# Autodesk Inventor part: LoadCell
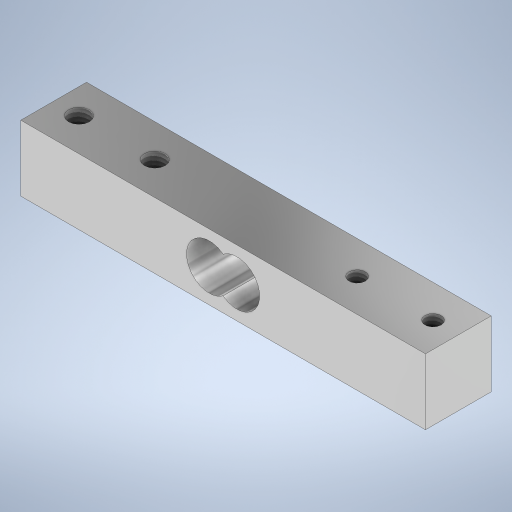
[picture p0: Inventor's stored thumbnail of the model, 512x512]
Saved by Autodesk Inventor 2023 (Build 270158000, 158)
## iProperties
Created: 2023-08
Part Number: LoadCell
Material: Generic
Document SubType Name: Modeling
Designer: Admin
Density: 1 g/cm^3
Appearance: Aluminum - Polished
Author: Admin
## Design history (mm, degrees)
sketch "Sketch1"
  geometry: L1 (0, 0)-(80, 0); L2 (80, 0)-(80, -13); L3 (80, -13)-(0, -13); L4 (0, -13)-(0, 0); L5 (80, -6.5)-(0, -6.5); C1 r 2 at (75, -6.5); C2 r 2 at (60, -6.5); C3 r 1.5 at (20, -6.5); C4 r 1.5 at (5, -6.5)
  constraints: 10 end point, 4 centre point, 3 horizontal alignment, 2 equal radius, 2 midpoint, 2 parallel, 1 horizontal, 1 perpendicular, 1 point on line
  dimensions: "d0" = 13 distance between parallel lines of L1 L3; "d1" = 15 distance of C1.centre C2.centre; "d2" = 80 distance between parallel lines of L4 L2; "d3" = 15 distance of C4.centre C3.centre; "d4" = 5 distance from line of L4 C4.centre; "d5" = 5 distance from line of L2 C1.centre; "d6" = 4 diameter of C1; "d7" = 3 diameter of C3
extrude "Extrusion1" new body sketch "Sketch1" distance "d8" = 13; taper "d9" = 0 deg
sketch "Sketch2"
  geometry: L1 (80, 0)-(80, 13) reference; L2 (80, 6.5)-(0, 6.5); L3 (0, 0)-(0, 13) reference; L4 (0, 13)-(80, 13) reference; L5 (40, 13)-(42.733, 6.5); L6 (37.267, 6.5)-(40, 13); C1 r 4.5 at (42.733, 6.5); C2 r 4.5 at (37.267, 6.5); 2 further points
  constraints: 6 end point, 3 midpoint, 2 centre point, 2 point on line, 1 equal length, 1 equal radius
  dimensions: "d10" = 9 diameter of C1
extrude "Extrusion2" cut sketch "Sketch2" stored distance "d11" = 13; taper "d12" = 0 deg
sketch "Sketch3"
  geometry: C1 r 2 at (-75, 6.5) reference; C2 r 2 at (-60, 6.5) reference; 3 further points
  constraints: 2 coincident
hole "Hole1" sketch "Sketch3" at (-75, 6.5), (-60, 6.5) diameter "d13" = 4.134; stored, may be unused: countersink angle "d17" = 90 deg, drill point angle "d19" = 118 deg; dims "d14" = 13, "d15" = 4, "d16" = 2, "d18" = 8
sketch "Sketch4"
  geometry: C1 r 1.5 at (-20, 6.5) reference; C2 r 1.5 at (-5, 6.5) reference; 3 further points
  constraints: 2 coincident
hole "Hole2" sketch "Sketch4" at (-20, 6.5), (-5, 6.5) diameter "d20" = 3.242; stored, may be unused: countersink angle "d24" = 90 deg, drill point angle "d26" = 0 deg; dims "d21" = 13, "d22" = 4, "d23" = 2, "d25" = 8
body "Solid1"
